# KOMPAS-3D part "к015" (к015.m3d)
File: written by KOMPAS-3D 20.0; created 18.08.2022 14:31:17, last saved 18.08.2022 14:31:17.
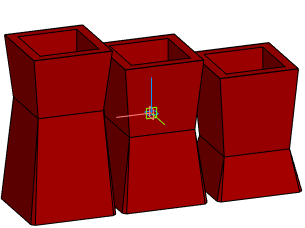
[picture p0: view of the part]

Document properties: Автор: artemsv220@gmail.com; Полное имя файла: \\192.168.2.25\новая общая папка\Медиа\Светильники\Кашпо\Кашпо и вазоны\DWG\к015.m3d

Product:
- Part/product: к015

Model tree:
1. Операция без истории:1
2. Операция без истории:2
3. Операция без истории:3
